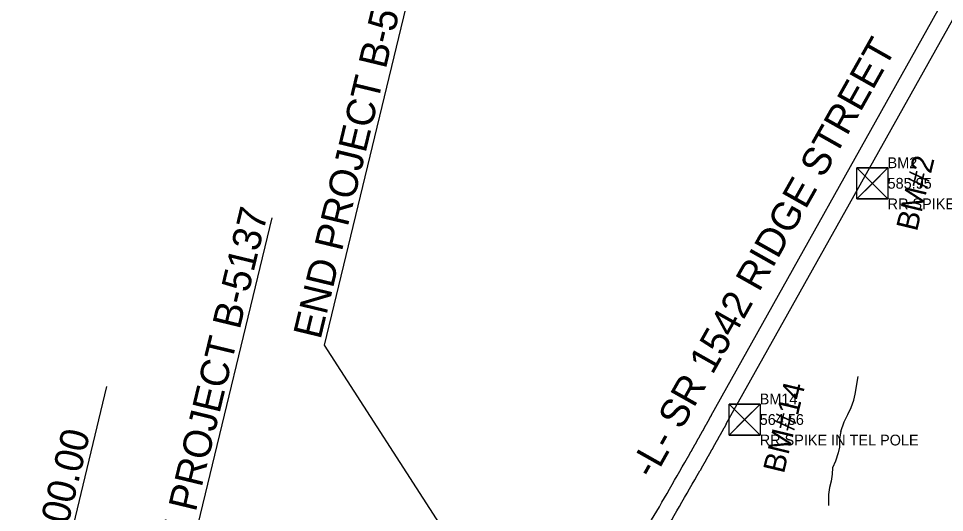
# Model space of a CAD drawing. Extents: x 1649669 to 1659218, y 588594 to 607900.
# Drawn here: x 1652859 to 1654574, y 598543 to 599457 of the extents above; entities that cross this region are included whole.
import ezdxf

# ---------------------------------------------------------------- set-up
doc = ezdxf.new("R2010")
doc.units = 0
for name, color, linetype in [('CTL Bench Mark CELL', 7, 'Continuous'), ('CTL Bench Mark Cogo Comment', 7, 'Continuous'), ('CTL Bench Mark Cogo Elevation', 7, 'Continuous'), ('CTL Bench Mark Cogo Number', 7, 'Continuous'), ('CTL Bench Mark Text', 7, 'Continuous'), ('CTL Sheet Notes CELL', 7, 'Continuous'), ('Default', 7, 'Continuous'), ('Exist Hydro Stream or Body of Water', 7, 'Continuous'), ('Exist Roads EOP', 7, 'Continuous'), ('Sheet Data Field CELL', 7, 'Continuous')]:
    doc.layers.add(name, color=color, linetype=linetype)

msp = doc.modelspace()

# ---------------------------------------------------------------- linework, layer by layer
at = {"layer": 'CTL Bench Mark CELL'}
for p, q in [((1654440.7, 599151.7), (1654440.7, 599151.7)), ((1654203.9, 598714.6), (1654203.9, 598714.6))]:
    msp.add_line(p, q, dxfattribs=at)
for points in [[(1654411.9, 599180.4), (1654469.4, 599180.4), (1654469.4, 599122.9), (1654411.9, 599122.9)], [(1654175.1, 598743.3), (1654232.6, 598743.3), (1654232.6, 598685.8), (1654175.1, 598685.8)]]:
    msp.add_lwpolyline(points, close=True, dxfattribs=at)
for points in [[(1654469.4, 599180.4), (1654411.9, 599122.9), (1654440.6, 599151.6), (1654469.4, 599122.9), (1654411.9, 599180.4)], [(1654440.6, 599151.6), (1654469.4, 599180.4), (1654411.9, 599180.4), (1654440.6, 599151.6)], [(1654440.6, 599151.6), (1654411.9, 599122.9), (1654469.4, 599122.9), (1654440.6, 599151.6)], [(1654232.6, 598743.3), (1654175.1, 598685.8), (1654203.9, 598714.6), (1654232.6, 598685.8), (1654175.1, 598743.3)], [(1654203.9, 598714.6), (1654232.6, 598743.3), (1654175.1, 598743.3), (1654203.9, 598714.6)], [(1654203.9, 598714.6), (1654175.1, 598685.8), (1654232.6, 598685.8), (1654203.9, 598714.6)]]:
    msp.add_lwpolyline(points, dxfattribs=at)
at = {"layer": 'Default'}
for p, q in [((1653425.8, 598852.2), (1653618.3, 599649.4)), ((1653136.5, 598290.4), (1653329, 599087.7)), ((1653850.9, 598193.8), (1653425.8, 598852.2)), ((1652867, 598128.7), (1653023.1, 598775.4))]:
    msp.add_line(p, q, dxfattribs=at)
at = {"layer": 'Exist Hydro Stream or Body of Water'}
for points in [[(1654382.2, 598692.3), (1654388.6, 598710.3), (1654395, 598723.9), (1654401.5, 598737.1), (1654406.1, 598750.3), (1654408.5, 598761.7), (1654414.3, 598794.3)], [(1654382.2, 598692.3), (1654379.4, 598679.7), (1654379.9, 598663.4), (1654377.3, 598652.7), (1654372.1, 598637.7), (1654367, 598624.9), (1654366.3, 598613.2), (1654364.4, 598600.6), (1654361, 598589.1), (1654359.6, 598575.8), (1654359.6, 598555.5)]]:
    msp.add_lwpolyline(points, dxfattribs=at)
at = {"layer": 'Exist Roads EOP'}
for p, q in [((1654170, 598706.6), (1654682.8, 599621.6)), ((1654142.1, 598722.2), (1654571.2, 599488))]:
    msp.add_line(p, q, dxfattribs=at)
for radius in [8984, 9016]:
    msp.add_arc((1646280.4, 603070.7), radius, 329.45173, 330.4149, dxfattribs=at)
for points in [[(1654142.1, 598722.2), (1654141.5, 598721), (1654140.8, 598719.9), (1654140.1, 598718.7), (1654139.5, 598717.5), (1654138.8, 598716.3), (1654138.2, 598715.2), (1654137.5, 598714), (1654136.8, 598712.8), (1654136.2, 598711.6), (1654135.5, 598710.4), (1654134.8, 598709.3), (1654134.2, 598708.1), (1654133.5, 598706.9), (1654132.9, 598705.7), (1654132.2, 598704.5), (1654131.5, 598703.4), (1654130.9, 598702.2), (1654130.2, 598701), (1654129.6, 598699.8), (1654128.9, 598698.7), (1654128.2, 598697.5), (1654127.6, 598696.3), (1654126.9, 598695.1), (1654126.3, 598693.9), (1654125.6, 598692.8), (1654124.9, 598691.6), (1654124.3, 598690.4), (1654123.6, 598689.2), (1654123, 598688.1), (1654122.3, 598686.9), (1654121.6, 598685.7), (1654121, 598684.5), (1654120.3, 598683.3), (1654119.6, 598682.2), (1654119, 598681), (1654118.3, 598679.8), (1654117.7, 598678.6), (1654117, 598677.5), (1654116.3, 598676.3), (1654115.7, 598675.1), (1654115, 598673.9), (1654114.4, 598672.8), (1654113.7, 598671.6), (1654113, 598670.4), (1654112.4, 598669.2), (1654111.7, 598668), (1654111, 598666.9), (1654110.4, 598665.7), (1654109.7, 598664.5), (1654109.1, 598663.3), (1654108.4, 598662.2), (1654107.7, 598661), (1654107.1, 598659.8), (1654106.4, 598658.6), (1654105.7, 598657.5), (1654105.1, 598656.3), (1654104.4, 598655.1), (1654103.7, 598653.9), (1654103.1, 598652.8), (1654102.4, 598651.6), (1654101.8, 598650.4), (1654101.1, 598649.2), (1654100.4, 598648.1), (1654099.8, 598646.9), (1654099.1, 598645.7), (1654098.4, 598644.5), (1654097.8, 598643.4), (1654097.1, 598642.2), (1654096.4, 598641), (1654095.8, 598639.8), (1654095.1, 598638.7), (1654094.4, 598637.5), (1654093.8, 598636.3), (1654093.1, 598635.2)], [(1654170, 598706.6), (1654169.4, 598705.4), (1654168.7, 598704.2), (1654168, 598703), (1654167.4, 598701.9), (1654166.7, 598700.7), (1654166.1, 598699.5), (1654165.4, 598698.3), (1654164.7, 598697.1), (1654164.1, 598696), (1654163.4, 598694.8), (1654162.8, 598693.6), (1654162.1, 598692.4), (1654161.4, 598691.3), (1654160.8, 598690.1), (1654160.1, 598688.9), (1654159.5, 598687.7), (1654158.8, 598686.5), (1654158.1, 598685.4), (1654157.5, 598684.2), (1654156.8, 598683), (1654156.2, 598681.8), (1654155.5, 598680.6), (1654154.8, 598679.5), (1654154.2, 598678.3), (1654153.5, 598677.1), (1654152.8, 598675.9), (1654152.2, 598674.7), (1654151.5, 598673.6), (1654150.9, 598672.4), (1654150.2, 598671.2), (1654149.5, 598670), (1654148.9, 598668.8), (1654148.2, 598667.7), (1654147.5, 598666.5), (1654146.9, 598665.3), (1654146.2, 598664.1), (1654145.6, 598663), (1654144.9, 598661.8), (1654144.2, 598660.6), (1654143.6, 598659.4), (1654142.9, 598658.2), (1654142.2, 598657.1), (1654141.6, 598655.9), (1654140.9, 598654.7), (1654140.2, 598653.5), (1654139.6, 598652.3), (1654138.9, 598651.2), (1654138.3, 598650), (1654137.6, 598648.8), (1654136.9, 598647.6), (1654136.3, 598646.5), (1654135.6, 598645.3), (1654134.9, 598644.1), (1654134.3, 598642.9), (1654133.6, 598641.7), (1654132.9, 598640.6), (1654132.3, 598639.4), (1654131.6, 598638.2), (1654130.9, 598637), (1654130.3, 598635.8), (1654129.6, 598634.7), (1654128.9, 598633.5), (1654128.3, 598632.3), (1654127.6, 598631.1), (1654126.9, 598630), (1654126.3, 598628.8), (1654125.6, 598627.6), (1654124.9, 598626.4), (1654124.3, 598625.2), (1654123.6, 598624.1), (1654122.9, 598622.9), (1654122.3, 598621.7), (1654121.6, 598620.5), (1654120.9, 598619.4)]]:
    msp.add_spline(points, degree=3, dxfattribs=at)

# ---------------------------------------------------------------- texts
at = {"layer": 'CTL Bench Mark Cogo Comment'}
for s, p in [('RR SPIKE IN 24" OAK', (1654468.7, 599103.7)), ('RR SPIKE IN TEL POLE', (1654231.9, 598666.6))]:
    msp.add_text(s, height=20, dxfattribs=at).set_placement(p)
at = {"layer": 'CTL Bench Mark Cogo Elevation'}
for s, p in [('585.95', (1654468.7, 599141.7)), ('564.56', (1654231.9, 598704.6))]:
    msp.add_text(s, height=20, dxfattribs=at).set_placement(p)
at = {"layer": 'CTL Bench Mark Cogo Number'}
for s, p in [('BM2', (1654468.7, 599179.7)), ('BM14', (1654231.9, 598742.6))]:
    msp.add_text(s, height=20, dxfattribs=at).set_placement(p)
at = {"layer": 'CTL Bench Mark Text'}
for s, p in [('BM#2', (1654523.1, 599061.3)), ('BM#14', (1654276.6, 598613.2))]:
    msp.add_text(s, height=40, rotation=76.4261, dxfattribs=at).set_placement(p)
at = {"layer": 'CTL Sheet Notes CELL'}
for s, p in [('3.    THIS PROJECT USES THE SAME DATUM AND COORDINATE SYSTEM AS TIP PROJECT U-3300B.', (1652431.3, 599171.9)), ('4.    THE ELEVATION OF U3300B-1 WAS REVISED BASED ON LEVELS RUN FOR B-5137 PROJECT.', (1652568.4, 599138.8))]:
    msp.add_text(s, height=52.174, rotation=76.4261, dxfattribs=at).set_placement(p)
at = {"layer": 'Sheet Data Field CELL'}
for s, rotation, p in [('END PROJECT B-5137', 76.4261, (1653418.5, 598861.2)), ('-L- SR 1542 RIDGE STREET', 60.5969, (1654035.2, 598602.2)), ('BEGIN PROJECT B-5137', 76.4261, (1653131.5, 598310.8)), ('-L- STA 10+00.00', 76.4261, (1652861.9, 598149.1))]:
    msp.add_text(s, height=52.501, rotation=rotation, dxfattribs=at).set_placement(p)

doc.saveas('drawing.dxf')
